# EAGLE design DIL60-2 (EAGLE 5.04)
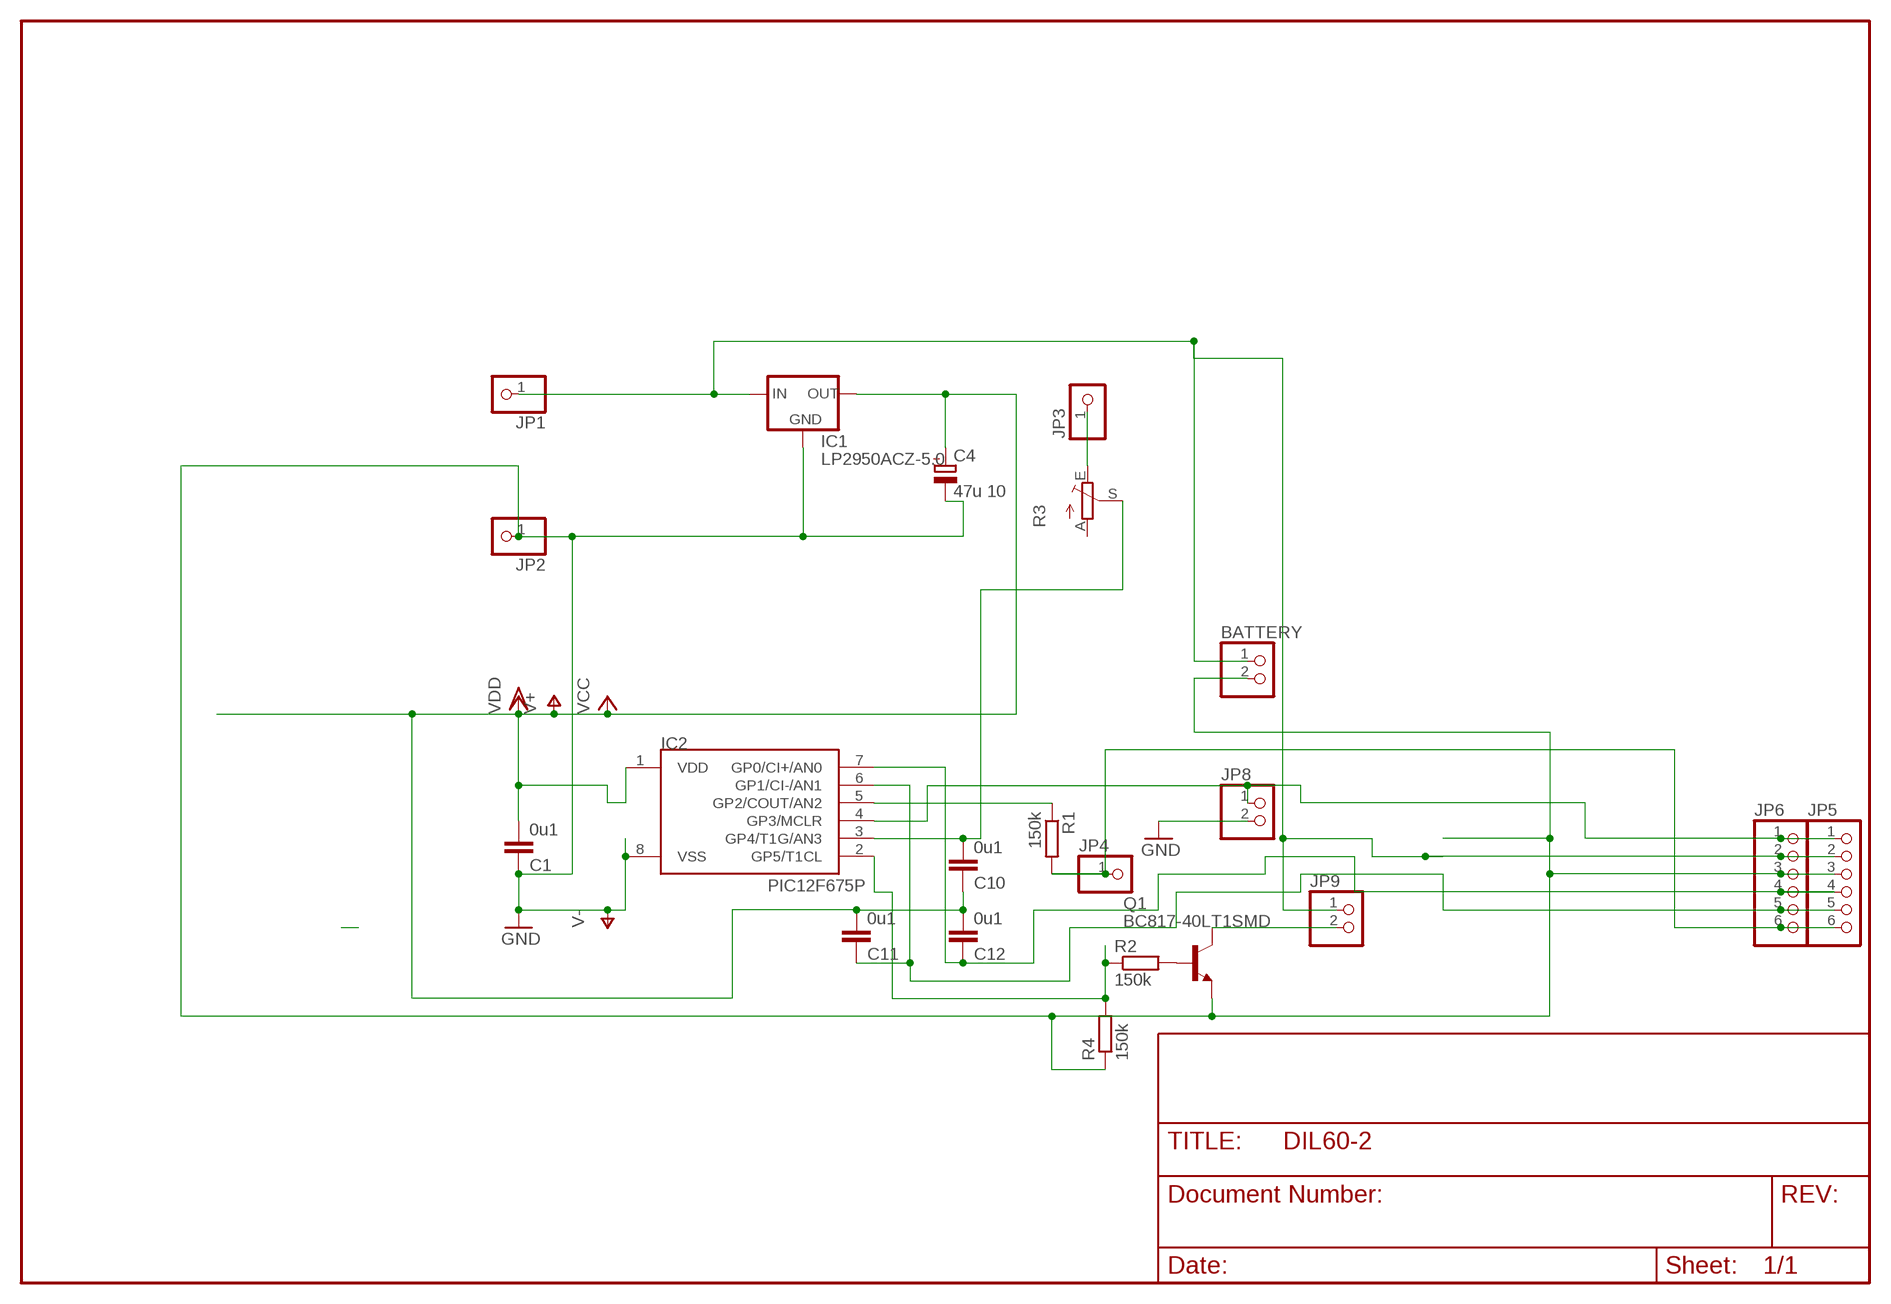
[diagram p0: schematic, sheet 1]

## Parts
BATTERY  PINHD-1X2  [1X02]
C1  0u1  C-EUC1206  [C1206]
C4  47u 10  CPOL-EUE2.5-6  [E2,5-6]
C10  0u1  C-EUC1206  [C1206]
C11  0u1  C-EUC1206  [C1206]
C12  0u1  C-EUC1206  [C1206]
IC1  LP2950ACZ-5.0  [TO92]
IC2  PIC12F675P  [DIL8]
JP1  PINHD-1X1  [1X01]
JP2  PINHD-1X1  [1X01]
JP3  PINHD-1X1  [1X01]
JP4  PINHD-1X1  [1X01]
JP5  PINHD-1X6  [1X06]
JP6  PINHD-1X6  [1X06]
JP8  PINHD-1X2  [1X02]
JP9  PINHD-1X2  [1X02]
Q1  BC817-40LT1SMD  [SOT23-BEC]
R1  150k  R-EU_R0805  [R0805]
R2  150k  R-EU_R0805  [R0805]
R3  TRIM_EU-CA6V  [CA6V]
R4  150k  R-EU_R0805  [R0805]

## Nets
GND: BATTERY.2 C1.1 C4.- IC1.2(GND) IC2.8(VSS) JP2.1 JP5.3 JP6.3 JP8.2 Q1.E R4.1 ; supply symbol labelled V-
N$1: JP3.1 R3.E
N$2: JP4.1 JP5.6 JP6.6 R1.2
N$3: IC2.4(GP3/MCLR) JP5.1 JP6.1 JP8.1
N$4: Q1.B R2.2
N$5: IC2.5(GP2/COUT/AN2) R1.1
N$8: IC2.2(GP5/T1CL) R2.1 R4.2
N$12: C10.2 IC2.3(GP4/T1G/AN3) R3.S
N$13: C12.1 IC2.7(GP0/CI+/AN0) JP5.4 JP6.4
N$14: JP9.2 Q1.C
N$15: C11.1 IC2.6(GP1/CI-/AN1) JP5.5 JP6.5
V+: C1.2 C4.+ C10.1 C11.2 C12.2 IC1.1(OUT) IC2.1(VDD) ; supply symbol labelled VDD, VCC
VDD: BATTERY.1 IC1.3(IN) JP1.1 JP5.2 JP6.2 JP9.1
Unconnected: R3.A

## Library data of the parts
BATTERY JP8 JP9 = pinhead:PINHD-1X2: PIN HEADER
C1 C10-C12 = rcl:C-EU: CAPACITOR, European symbol
C4 = rcl:CPOL-EU: POLARIZED CAPACITOR, European symbol
IC1 = v-reg:LP2950?*: Source: http://cache.national.com/ds/LP/LP2950.pdf
IC2 = microchip-3:PIC12F6*: uPC nW 1k Program Flash memory 2x Timer Comparator 10b A/D converter/ 4xIN
JP1-JP4 = pinhead:PINHD-1X1: PIN HEADER
JP5 JP6 = pinhead:PINHD-1X6: PIN HEADER
Q1 = transistor-npn:BC817*: NPN Transistor
R1 R2 R4 = rcl:R-EU_: RESISTOR, European symbol
R3 = pot:TRIM_EU-: POTENTIOMETER

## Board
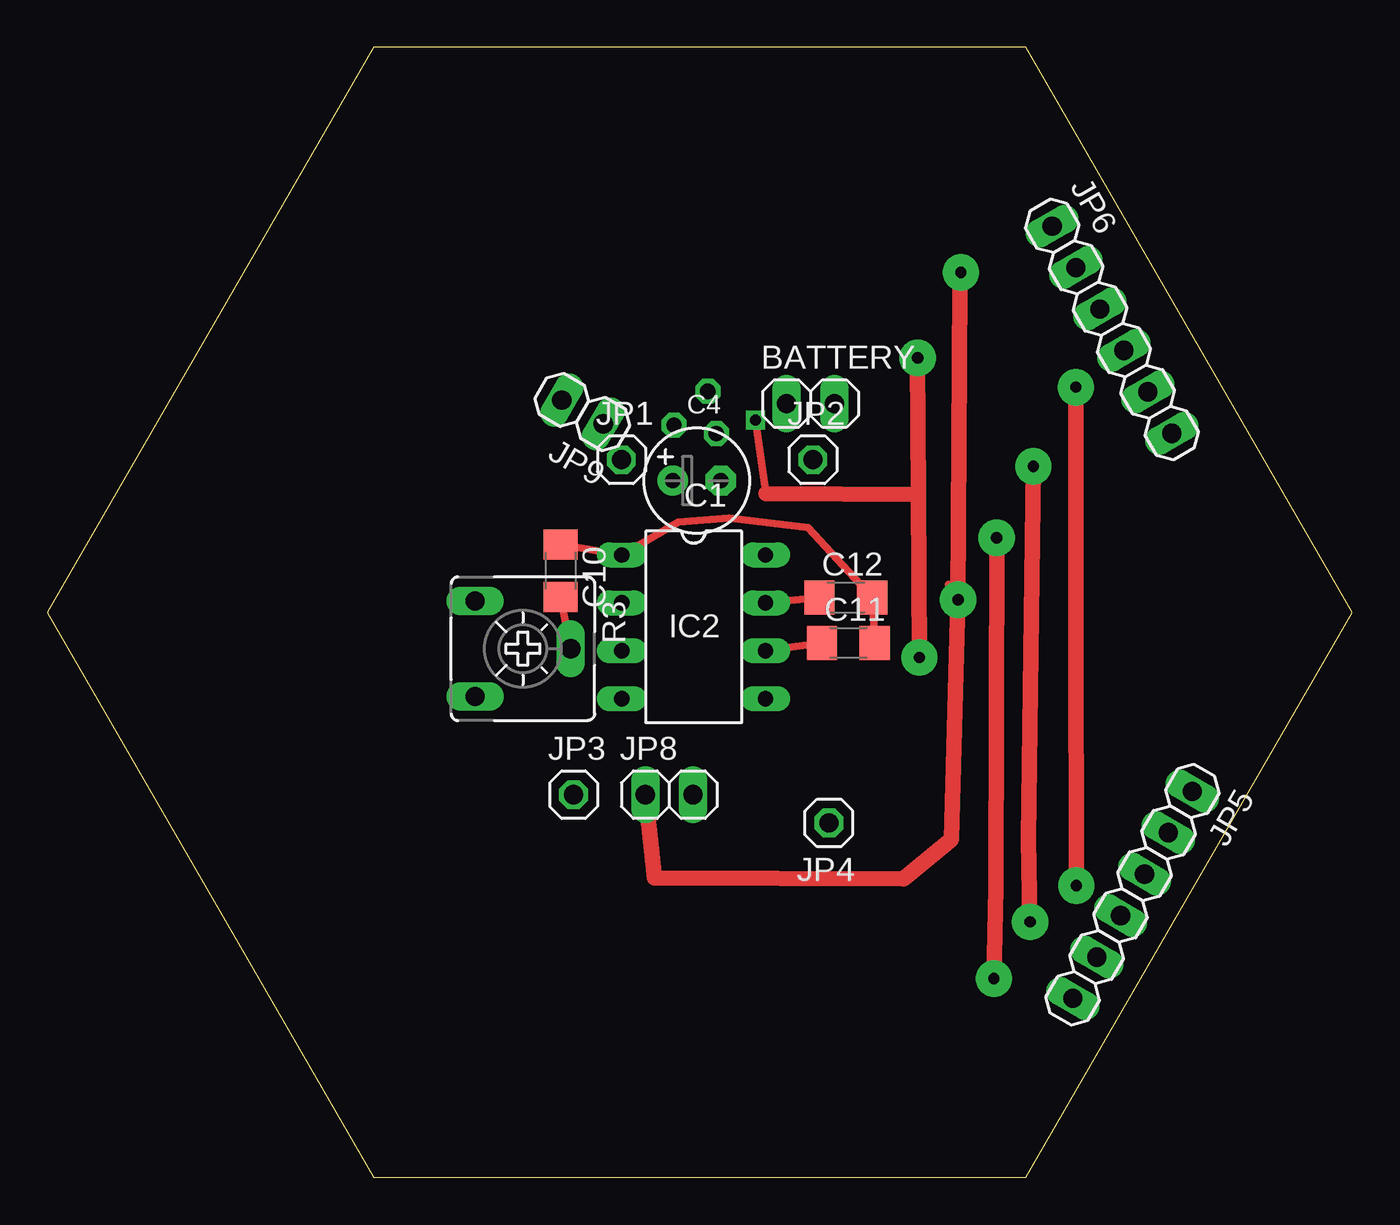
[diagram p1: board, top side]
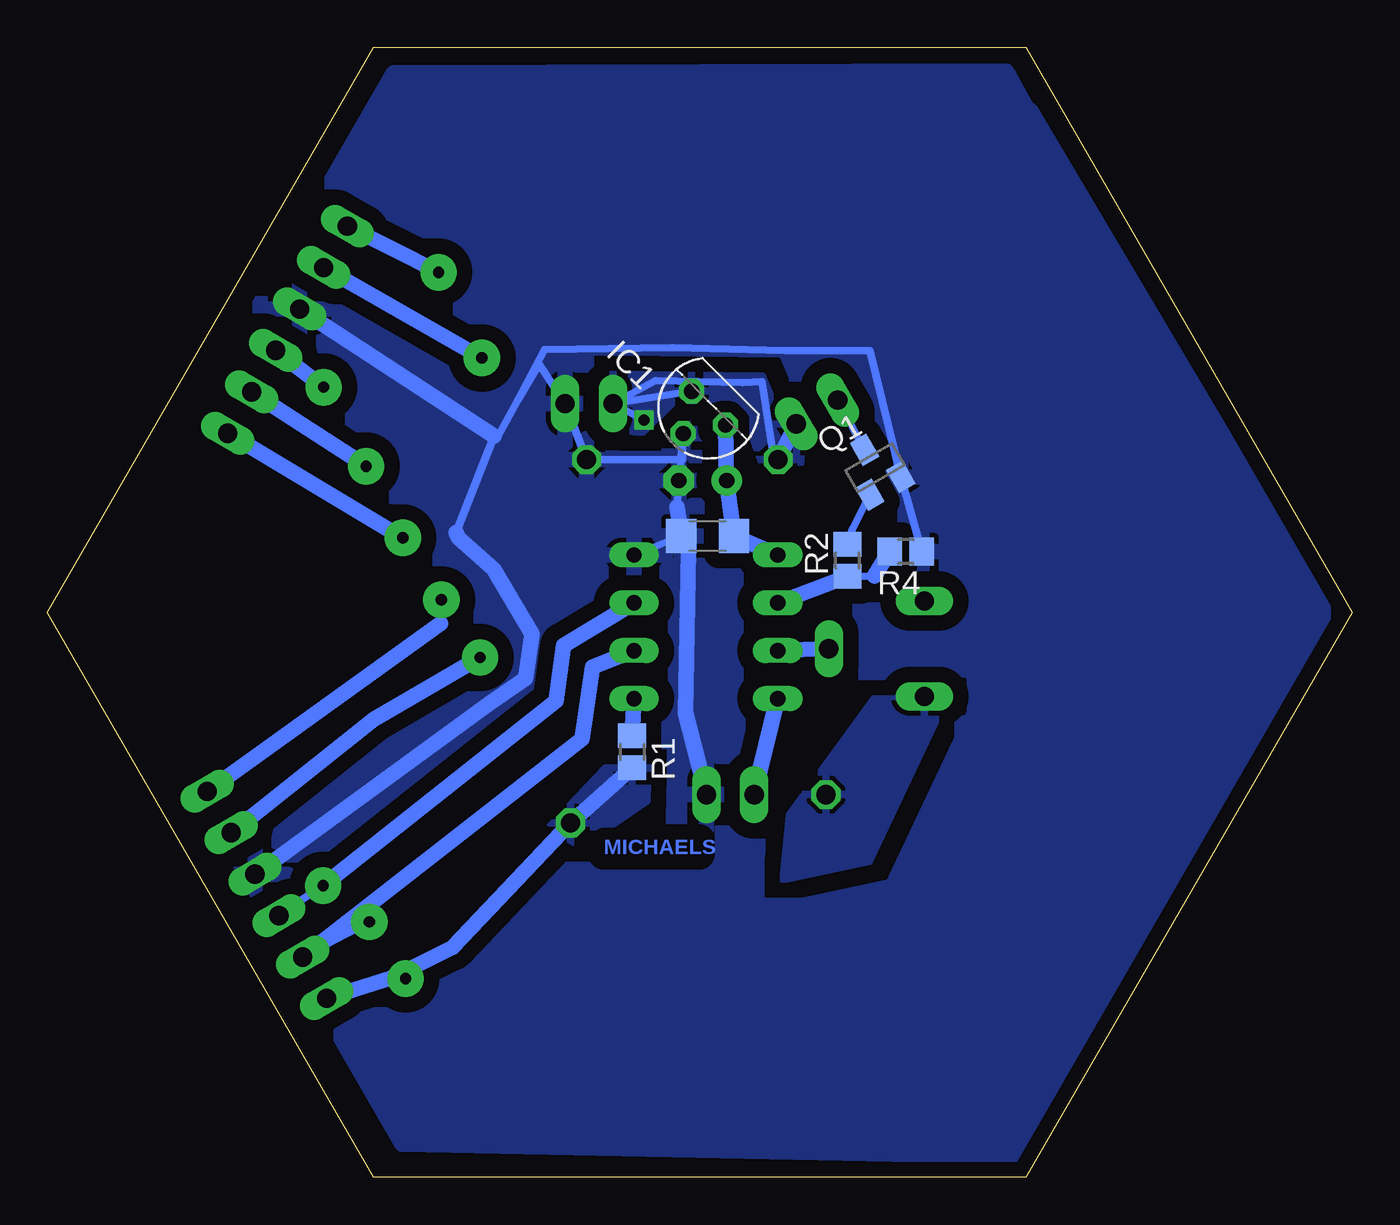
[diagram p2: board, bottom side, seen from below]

Size 69.28 x 60 mm. Coordinates in mm from the lower left corner, seen from the top.
Outline: 17.32,0 51.96,0 69.28,30 51.96,60 17.32,60 0,30 17.32,0
Copper layers (1*16): Top 0.035mm / dielectric 1.5mm / Bottom 0.035mm
Design rules "default *": minimum track width 10mil, minimum drill 24mil, track to track 8mil, track to pad 8mil, pad to pad 8mil, via to via 8mil, smd to smd 8mil, copper to edge 10mil, drill to drill 8mil, minimum pad ring 10mil, minimum via ring 8mil, stop-mask expansion 4mil, vias tented up to drill 0mil, thermal gap 10mil

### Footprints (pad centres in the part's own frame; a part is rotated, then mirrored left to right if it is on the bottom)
1X02 = drill 1.016 long: 1 -1.27,0; 2 1.27,0
C1206 = smd 1.6 x 1.8: 1 -1.4,0; 2 1.4,0
E2,5-6 = drill 0.813 pad 1.6 round: + -1.27,0 | drill 0.813 pad 1.6 octagon: - 1.27,0
TO92 = drill 0.813 octagon: 1 -1.27,0; 2 0,1.905; 3 1.27,0
DIL8 = drill 0.813 long: 1 -3.81,-3.81; 2 -1.27,-3.81; 3 1.27,-3.81; 4 3.81,-3.81; 5 3.81,3.81; 6 1.27,3.81; 7 -1.27,3.81; 8 -3.81,3.81
1X01 = drill 1.016 octagon: 1 0,0
1X06 = drill 1.016 long: 1 -6.35,0; 2 -3.81,0; 3 -1.27,0; 4 1.27,0; 5 3.81,0; 6 6.35,0
SOT23-BEC = smd 1 x 1.4: B -0.95,-1.1; C 0,1.1; E 0.95,-1.1
R0805 = smd 1.3 x 1.5: 1 -0.85,0; 2 0.85,0
CA6V = drill 1.016 long: A -2.54,-2.54; E 2.54,-2.54; S 0,2.54

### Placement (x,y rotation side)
BATTERY  40.52,41.08 0 top
C1  34.22,34.05 0 bottom
C4  34.48,36.99 0 top
C10  27.25,32.2 270 top
C11  42.53,28.38 0 top
C12  42.39,30.78 0 top
IC1  34.17,40.84 135 bottom
IC2  34.32,29.23 270 top
JP1  30.48,38.1 0 top
JP2  40.64,38.1 0 top
JP3  27.94,20.32 0 top
JP4  41.5,18.82 180 top
JP5  57.61,15 240 top
JP6  56.52,45 300 top
JP8  33.02,20.32 0 top
JP9  28.42,40.64 150 top
Q1  25.34,37.67 30 bottom
R1  38.23,22.59 270 bottom
R2  26.8,32.75 90 bottom
R3  25.25,28.07 270 top
R4  23.71,33.22 180 bottom

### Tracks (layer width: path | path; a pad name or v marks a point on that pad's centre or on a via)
GND
  Bottom 0.406: 35.85,35.59 C4.- IC1.2 35.56,38.1 JP2.1 BATTERY.2 43.18,43.18 44.32,41.25 | 47.58,34.24 45.56,39.36 45.36,39.29 44.32,41.25 | 44.32,41.25 42.88,43.94 36.08,44.04 30.08,43.89 25.6,43.9 Q1.E R4.1 | IC2.8 C1.1 35.25,33.3
  Bottom 0.813: C1.1 35.85,35.59 | 47.58,34.24 47.43,33.94 45.58,32.29 43.53,28.84 43.88,26.49 45.78,25.19 JP5.3 | JP8.2 35.4,24.65 35.25,33.3 | 45.56,39.36 JP6.3
  pour Bottom (isolate 0.813, rank 6): 18.4,58.75 50.9,58.65 67.1,30.6 50.45,1.75 17.95,1.1 1.3,30.05 17.1,56.65 17.1,56.45 18.25,58.55
N$1
  pour Bottom (isolate 0.61): 22.86,25.4 25.4,25.4 29.88,19.24 30.23,15.79 25.63,16.79 21.48,25.59
N$2  (via drill 0.6 pad 1.93)
  Top 0.813: v50.4,33.95 50.35,15.35 v50.25,10.55
  Bottom 0.406: 50.99,10.6 v50.25,10.55
  Bottom 0.813: R1.2 JP4.1 47.77,12.21 50.99,10.6 JP5.6 | v50.4,33.95 JP6.6
  pour Bottom (isolate 0.61): 40.64,17.78 37.43,19.99 37.38,21.89 39.63,21.74 42.63,18.59 41.08,17.64
N$3  (via drill 0.6 pad 1.93)
  Top 0.406: 48.45,47.35 v48.5,48.05 | v48.35,30.66 47.83,31.46
  Top 0.813: 48.45,47.35 v48.35,30.66 48,17.95 45.45,15.85 32.25,15.9 JP8.1
  Bottom 0.406: v48.35,30.66 48.4,29.4
  Bottom 0.813: v48.5,48.05 JP6.1 | 48.4,29.4 JP5.1 | JP8.1 IC2.4
N$4
  Bottom 0.406: Q1.B 26.54,34.41 R2.2
N$5
  Bottom 0.813: R1.1 IC2.5
N$8
  Bottom 0.406: 25.38,31.93 R2.1
  Bottom 0.813: R2.1 IC2.2 | 25.38,31.93 R4.2
N$12
  Top 0.406: R3.S C10.2
  Bottom 0.813: R3.S IC2.3
N$13  (via drill 0.6 pad 1.93)
  Top 0.406: IC2.7 C12.1
  Top 0.813: v54.6,41.95 54.61,29.52 v54.63,15.5
  Bottom 0.406: v54.63,15.5 JP5.4 v54.63,15.5
  Bottom 0.813: IC2.7 41.88,28.24 42.28,25.29 v54.63,15.5 | v54.6,41.95 JP6.4
N$14
  Bottom 0.406: Q1.C JP9.2
N$15  (via drill 0.6 pad 1.93)
  Top 0.406: IC2.6 C11.1
  Top 0.813: v52.35,37.75 52.1,17.95 v52.17,13.57
  Bottom 0.406: JP5.5 v52.17,13.57
  Bottom 0.813: IC2.6 40.33,27.09 40.88,23.28 JP5.5 | v52.35,37.75 JP6.5
V+
  Top 0.406: C10.1 IC2.1 33.5,34.8 36.2,35 40.38,34.51 C12.2 C11.2
  Bottom 0.813: IC2.1 C1.2 C4.+ IC1.1
VDD  (via drill 0.6, 0.6 pad 1.93)
  Top 0.406: v37.6,40.2 38.15,36.3
  Top 0.813: 46.25,36.25 v46.3,27.6 | 38.15,36.3 46.25,36.25 | 46.25,36.25 v46.2,43.5
  Bottom 0.406: JP1.1 30.7,38.1 31.35,42.25 32.35,42.2 37,42.3 BATTERY.1 | BATTERY.1 IC1.3 | BATTERY.1 v37.6,40.2
  Bottom 0.813: v46.3,27.6 51.95,24.3 JP5.2 | JP9.1 JP1.1 | v46.2,43.5 JP6.2
  pour Bottom (isolate 0.61): 30.48,40.64 31.3,42.55 39.7,42.65 39.85,39.85 37.7,39.5 35.95,41.25 32.5,41.25 31.2,37.55 29.9,37.5 29.3,37.9 29.2,38.65 29.35,38.6 30.05,39.85

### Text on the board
Bottom: MICHAELS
